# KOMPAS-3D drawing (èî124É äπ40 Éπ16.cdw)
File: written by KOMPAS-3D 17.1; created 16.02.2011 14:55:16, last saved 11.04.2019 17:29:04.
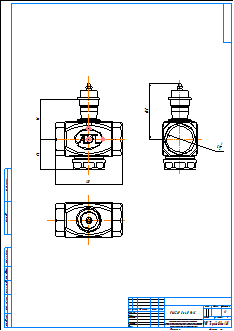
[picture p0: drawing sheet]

Title block, sheet 1: name: КМ124Р Ду40 Ру16; material: Внимание! Данный продукт является объектом авторского права ООО «Торговый Дом АДЛ». / Запрещается изменение, копирование, распространение / (в том числе путем копирования на другие сайты и ресурсы в Интернете) / или любое иное использование информации и объектов без предварительного / согласия правообладателя (ООО «Торговый Дом АДЛ»).; scale: 1:1; sheets: 1; organisation: ООО "Торговый дом АДЛ"; sheet format: A2; stored path: \\adlc.lan\data\АДЛ_ПКД\3D-модели\ADL production\Клапаны ГРАНРЕГ\Двухходовой клапан KM124P\KOMPAS 2D\КМ124Р Ду40 Ру16.cdw

Views: Спереди 1, Проекционный вид 2, Проекционный вид 3
Dimensions and other numbers on the sheet: 54; 72; 101; 120; 1:1; 1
